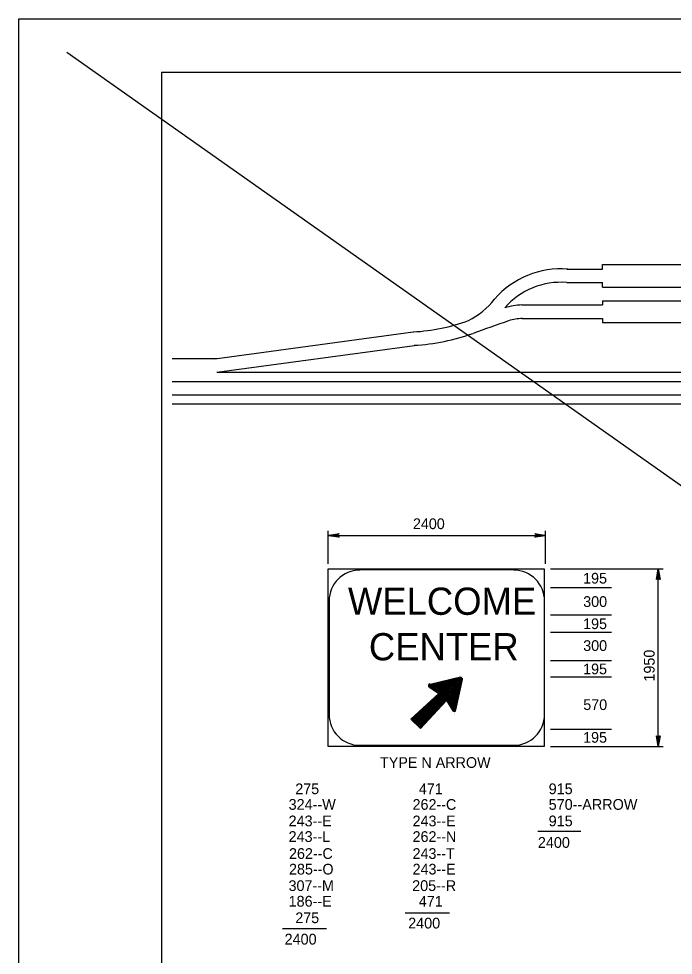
# Model space of a CAD drawing. Extents: x 2189973 to 2192941, y 2147557 to 2151454.
# Drawn here: x 2189973 to 2190575, y 2150594 to 2151454 of the extents above; entities that cross this region are included whole.
import ezdxf

# ---------------------------------------------------------------- set-up
doc = ezdxf.new("R2010")
doc.units = 0
for name, color, linetype in [('1', 7, 'Continuous'), ('Default', 7, 'Continuous'), ('PLT-BNDY', 7, 'Continuous')]:
    doc.layers.add(name, color=color, linetype=linetype)

# ---------------------------------------------------------------- blocks, each defined once
blk = doc.blocks.new('RARROW')
at = {"layer": 'Default'}
blk.add_lwpolyline([(-18.156, 2.28), (-17.479, 0.966), (0, 0), (-18.156, 2.28), (-19.086, 3.077), (0, 0), (-17.465, -0.864), (-18.103, -2.164), (0, 0), (-19.086, -3.033), (-18.103, -2.164)], dxfattribs=at)

msp = doc.modelspace()

# ---------------------------------------------------------------- linework, layer by layer
at = {"layer": '1'}
msp.add_line((2190017.34, 2151423.79), (2192695.57, 2149534.55), dxfattribs=at)
at = {"layer": 'Default'}
for p, q in [((2190104.48, 2151405.2), (2192683.21, 2151405.2)), ((2190104.48, 2151405.2), (2190104.48, 2149554.81)), ((2190510.07, 2151228.44), (2190584.3, 2151228.44)), ((2190510.07, 2151224.34), (2190510.07, 2151228.44)), ((2190477.26, 2151224.34), (2190510.07, 2151224.34)), ((2190477.26, 2151212.04), (2190510.07, 2151212.04)), ((2190510.07, 2151207.53), (2190510.07, 2151212.04)), ((2190510.07, 2151207.53), (2190584.3, 2151207.53)), ((2190510.07, 2151195.22), (2190584.3, 2151195.22)), ((2190510.07, 2151195.22), (2190510.07, 2151191.53)), ((2190435.84, 2151191.53), (2190510.07, 2151191.53)), ((2190435.84, 2151178.82), (2190510.07, 2151178.82)), ((2190510.07, 2151178.82), (2190510.07, 2151175.13)), ((2190510.07, 2151175.13), (2190584.3, 2151175.13)), ((2190153.69, 2151141.91), (2190335.78, 2151166.52)), ((2190155.33, 2151129.61), (2190337.01, 2151154.21)), ((2190337.01, 2151154.21), (2190337.01, 2151154.21)), ((2190337.01, 2151154.21), (2190337.01, 2151154.21)), ((2190155.33, 2151141.91), (2190114.32, 2151141.91)), ((2190155.33, 2151129.61), (2190939.04, 2151129.61)), ((2190155.33, 2151129.61), (2190155.33, 2151129.61)), ((2190155.33, 2151129.61), (2190155.33, 2151129.61)), ((2190114.32, 2151121), (2192679.93, 2151121)), ((2190114.32, 2151108.69), (2192679.93, 2151108.69)), ((2190114.32, 2151100.49), (2192679.93, 2151100.49)), ((2190257.86, 2150953.26), (2190257.86, 2150983.61)), ((2190257.86, 2150979.51), (2190457.58, 2150979.51)), ((2190457.58, 2150953.26), (2190457.58, 2150983.61)), ((2190462.09, 2150948.75), (2190565.73, 2150948.75)), ((2190561.21, 2150785.53), (2190561.21, 2150948.75)), ((2190462.09, 2150931.53), (2190518.12, 2150931.53)), ((2190258.68, 2150919.63), (2190258.68, 2150814.65)), ((2190456.76, 2150814.65), (2190456.76, 2150919.63)), ((2190462.09, 2150906.51), (2190518.12, 2150906.51)), ((2190462.09, 2150890.52), (2190518.12, 2150890.52)), ((2190462.09, 2150864.68), (2190518.12, 2150864.68)), ((2190379.25, 2150849.1), (2190351.36, 2150842.53)), ((2190381.3, 2150849.51), (2190381.3, 2150849.51)), ((2190462.09, 2150849.51), (2190518.12, 2150849.51)), ((2190348.08, 2150842.12), (2190348.08, 2150842.12)), ((2190350.95, 2150840.07), (2190359.56, 2150834.33)), ((2190375.15, 2150819.16), (2190380.89, 2150846.64)), ((2190359.56, 2150834.33), (2190333.73, 2150810.55)), ((2190359.56, 2150834.33), (2190359.56, 2150834.33)), ((2190342.75, 2150801.93), (2190366.54, 2150827.77)), ((2190366.54, 2150827.77), (2190366.54, 2150827.77)), ((2190366.54, 2150827.77), (2190372.28, 2150818.34)), ((2190374.33, 2150815.06), (2190374.33, 2150815.06)), ((2190333.73, 2150810.55), (2190342.75, 2150801.93)), ((2190462.09, 2150801.52), (2190518.12, 2150801.52)), ((2190462.09, 2150785.53), (2190565.73, 2150785.53)), ((2190450.57, 2150707.61), (2190489.94, 2150707.61)), ((2190328.38, 2150632.69), (2190369.39, 2150632.69)), ((2190215.62, 2150618.21), (2190256.22, 2150618.21))]:
    msp.add_line(p, q, dxfattribs=at)
msp.add_lwpolyline([(2190257.86, 2150785.53), (2190257.86, 2150948.75), (2190456.35, 2150948.75), (2190456.35, 2150785.53)], close=True, dxfattribs=at)
for points in [[(2190428.46, 2150947.93), (2190286.98, 2150947.93)], [(2190334.14, 2150810.96), (2190360.8, 2150834.74), (2190350.95, 2150840.89), (2190350.54, 2150841.3), (2190351.36, 2150842.53), (2190379.66, 2150848.69), (2190380.89, 2150848.28), (2190380.89, 2150847.05), (2190374.74, 2150819.16), (2190373.92, 2150818.34), (2190372.69, 2150818.75), (2190366.54, 2150828.18), (2190342.75, 2150802.34), (2190334.96, 2150810.55), (2190361.21, 2150834.74), (2190350.95, 2150841.3), (2190350.95, 2150841.3), (2190351.36, 2150842.53), (2190379.66, 2150848.28), (2190380.07, 2150847.87), (2190380.48, 2150847.05), (2190374.33, 2150819.57), (2190373.51, 2150818.75), (2190372.69, 2150818.75), (2190366.54, 2150828.59), (2190342.34, 2150802.75), (2190335.37, 2150810.55), (2190361.62, 2150834.33), (2190351.36, 2150841.3), (2190351.36, 2150841.71), (2190351.36, 2150842.12), (2190380.07, 2150847.46), (2190373.51, 2150819.16), (2190366.54, 2150829.41), (2190342.34, 2150803.16), (2190336.19, 2150810.55), (2190361.62, 2150834.33), (2190351.36, 2150841.71), (2190379.66, 2150847.05)], [(2190351.77, 2150841.3), (2190379.66, 2150846.64), (2190373.51, 2150819.57), (2190366.54, 2150830.64), (2190341.93, 2150803.57), (2190336.6, 2150810.55), (2190362.03, 2150834.74), (2190353.41, 2150841.3), (2190378.84, 2150846.23), (2190373.1, 2150820.39), (2190366.95, 2150831.46), (2190341.93, 2150804.81), (2190337.83, 2150810.55), (2190362.85, 2150834.74), (2190355.05, 2150840.89), (2190378.02, 2150845.41), (2190372.69, 2150822.03), (2190366.95, 2150831.87), (2190341.93, 2150805.22), (2190338.65, 2150810.96), (2190363.26, 2150834.74), (2190356.69, 2150840.48), (2190377.61, 2150845), (2190372.28, 2150823.67), (2190366.95, 2150832.28), (2190342.34, 2150806.45), (2190339.47, 2150810.96), (2190364.08, 2150834.74), (2190357.92, 2150840.07), (2190376.79, 2150843.76), (2190372.28, 2150824.9), (2190366.95, 2150833.1), (2190342.34, 2150807.68), (2190340.7, 2150810.96), (2190364.49, 2150834.74), (2190359.15, 2150839.66), (2190375.97, 2150842.94), (2190371.87, 2150826.54), (2190366.95, 2150833.51), (2190342.75, 2150809.32), (2190342.34, 2150808.91), (2190341.11, 2150810.55), (2190365.31, 2150834.74), (2190360.8, 2150839.25), (2190375.15, 2150842.53), (2190371.05, 2150827.77), (2190366.95, 2150833.92), (2190342.34, 2150809.32), (2190341.52, 2150810.55), (2190366.13, 2150834.74), (2190362.03, 2150839.25), (2190373.92, 2150841.71), (2190371.05, 2150829.41), (2190366.95, 2150834.74), (2190341.93, 2150809.73), (2190341.93, 2150810.55), (2190366.54, 2150834.74), (2190362.85, 2150838.84), (2190373.51, 2150841.3), (2190371.05, 2150830.23), (2190364.08, 2150838.43), (2190372.69, 2150840.48), (2190370.64, 2150831.46), (2190365.31, 2150838.43), (2190371.87, 2150839.25), (2190370.23, 2150831.87), (2190366.13, 2150837.61), (2190371.05, 2150838.84), (2190370.23, 2150833.51), (2190367.36, 2150837.2), (2190370.64, 2150838.43), (2190369.82, 2150834.74), (2190368.59, 2150836.79), (2190369.82, 2150837.2), (2190369.41, 2150835.97)], [(2190286.98, 2150786.76), (2190428.46, 2150786.76)]]:
    msp.add_lwpolyline(points, dxfattribs=at)
for centre, radius, start, end in [((2190471.58, 2151144.03), 80.51, 85.41339, 139.1043), ((2190471.58, 2151144.03), 68.14, 85.41339, 139.1043), ((2190354.97, 2151239.81), 70.46, 296.87931, 322.31094), ((2190439.28, 2151123.76), 67.66, 92.95256, 106.48658), ((2190325.5, 2151348.62), 182.36, 273.3346, 289.66361), ((2198936.79, 2127087.3), 25549.51, 109.463364, 109.540836), ((2190439.28, 2151123.76), 55.29, 92.95256, 106.48658), ((2190325.5, 2151348.62), 194.73, 273.3346, 289.66361), ((2190286.87, 2150919.28), 28.33, 90, 180), ((2190428.37, 2150919.28), 28.33, 0, 90), ((2190379.6, 2150847.32), 1.57, 348.09575, 101.90426), ((2190379.6, 2150847.32), 1.57, 348.09575, 101.90425), ((2190351.55, 2150841.41), 1.57, 101.90425, 237.30801), ((2190351.55, 2150841.41), 1.57, 101.90425, 237.30804), ((2190286.87, 2150814.9), 28.33, 180, 270), ((2190373.69, 2150819.27), 1.57, 212.69199, 348.09575), ((2190373.69, 2150819.27), 1.57, 212.69196, 348.09575), ((2190428.37, 2150814.9), 28.33, 270, 0)]:
    msp.add_arc(centre, radius, start, end, dxfattribs=at)
at = {"layer": 'PLT-BNDY'}
msp.add_lwpolyline([(2189973.25, 2151454.41), (2192732.43, 2151454.41), (2192732.43, 2149505.6), (2189973.25, 2149505.6)], close=True, dxfattribs=at)

# ---------------------------------------------------------------- block references
at = {"layer": 'Default', "xscale": 0.515679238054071, "yscale": 0.5369477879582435}
for p, rotation in [((2190257.86, 2150979.51), 180), ((2190561.21, 2150948.75), 89.99999999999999), ((2190561.21, 2150785.53), -90.00000000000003)]:
    msp.add_blockref('RARROW', p, dxfattribs=dict(at, rotation=rotation))
msp.add_blockref('RARROW', (2190457.58, 2150979.51), dxfattribs=at)

# ---------------------------------------------------------------- texts
at = {"layer": 'Default'}
for s, height, p in [('2400', 9.842, (2190335.65, 2150985.3)), ('195', 9.842, (2190492.12, 2150935.24)), ('300', 9.842, (2190492.21, 2150913.77)), ('195', 9.842, (2190492.12, 2150893.4)), ('300', 9.842, (2190492.21, 2150873.31)), ('195', 9.842, (2190492.12, 2150851.84)), ('570', 9.842, (2190492.27, 2150819.01)), ('195', 9.842, (2190492.12, 2150788.95)), ('TYPE N ARROW', 9.8425, (2190305.43, 2150765.84)), ('275  ', 9.842, (2190227.51, 2150741.65)), ('471    ', 9.842, (2190341.11, 2150741.65)), ('915       ', 9.894, (2190460.45, 2150741.65)), (' 324--W', 9.894, (2190217.67, 2150727.29)), (' 262--C', 9.842, (2190331.68, 2150727.29)), ('570--ARROW', 9.894, (2190460.45, 2150727.29)), (' 243--E', 9.894, (2190217.67, 2150712.12)), (' 243--E', 9.842, (2190331.68, 2150712.12)), ('915       ', 9.894, (2190460.45, 2150712.12)), (' 243--L', 9.894, (2190217.67, 2150697.77)), (' 262--N', 9.842, (2190331.68, 2150697.77)), ('2400        ', 9.8942, (2190450.53, 2150692.34)), (' 262--C', 9.842, (2190218.08, 2150682.18)), (' 243--T', 9.842, (2190331.68, 2150682.18)), (' 285--O', 9.842, (2190218.08, 2150667.83)), (' 243--E', 9.842, (2190331.68, 2150667.83)), (' 307--M', 9.842, (2190217.67, 2150652.66)), (' 205--R', 9.894, (2190331.27, 2150652.66)), (' 186--E', 9.894, (2190217.67, 2150638.3)), ('471    ', 9.842, (2190341.11, 2150638.3)), ('275  ', 9.842, (2190227.51, 2150623.13)), ('2400     ', 9.894, (2190331.27, 2150618.21)), ('2400   ', 9.894, (2190217.67, 2150603.44))]:
    msp.add_text(s, height=height, dxfattribs=at).set_placement(p)
for s, height, rotation, p in [('WELCOME', 25.047, 360, (2190275.9, 2150906.51)), ('CENTER', 25.047, 360, (2190295.18, 2150864.68)), ('1950', 9.842, 90, (2190557.85, 2150845.19))]:
    msp.add_text(s, height=height, rotation=rotation, dxfattribs=at).set_placement(p)

doc.saveas('drawing.dxf')
